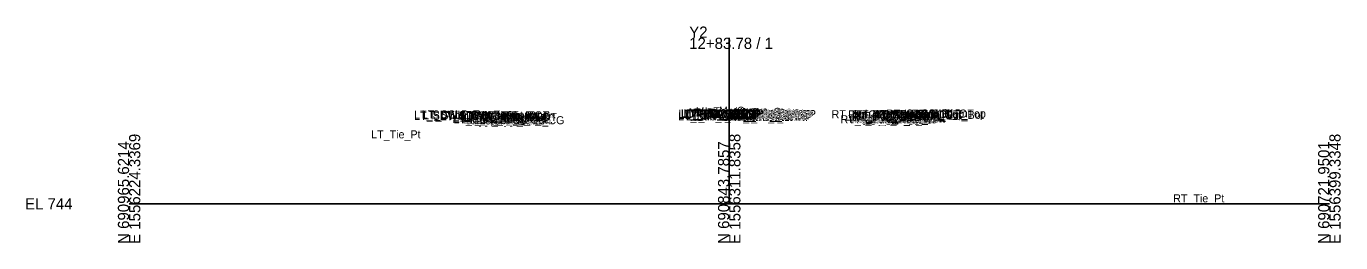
# Model space of a CAD drawing. Extents: x -26 to 4229, y -10 to 9523.
# Drawn here: x -25.7 to 302.8, y 2990.3 to 3044.3 of the extents above; entities that cross this region are included whole.
import ezdxf

# ---------------------------------------------------------------- set-up
doc = ezdxf.new("R2010")
doc.units = 0
doc.layers.add('Default', color=7, linetype='Continuous')
doc.layers.add('Exist Cross Section Cell', color=7, linetype='Continuous')

msp = doc.modelspace()

# ---------------------------------------------------------------- linework, layer by layer
at = {"layer": 'Exist Cross Section Cell'}
for p, q in [((150, 3000), (150, 3041.45)), ((0, 3000), (150, 3000)), ((150, 3000), (300, 3000))]:
    msp.add_line(p, q, dxfattribs=at)

# ---------------------------------------------------------------- texts
at = {"layer": 'Default'}
for s, height, p in [('LT_SDWK_Out_Top', 2, (71.24, 3021.29)), ('LT_SDWK_Out_Bot', 2, (71.27, 3020.96)), ('LT_CSLP_Pnt', 2, (73.17, 3021.32)), ('LT_Sub_Trench_Out_DLT', 2, (73.49, 3021.12)), ('LT_SDWK_In_Top', 2, (77.86, 3021.19)), ('LT_SDWK_In_Bot', 2, (77.89, 3020.86)), ('LT_CG_Top_Face', 2, (82.76, 3021.08)), ('LT_CG_Top_BOC', 2, (83.28, 3021.08)), ('LT_CG_Top_Gut', 2, (83.74, 3020.58)), ('LT_PV1_OEOT', 2, (88.24, 3020.7)), ('LT_Sub_OEEOP', 2, (137.22, 3020.83)), ('LT_PV2_OEEOP', 2, (137.32, 3021.46)), ('LT_PV3_OEEOP', 2, (137.32, 3021.21)), ('LT_PV1_OEEOP', 2, (137.88, 3021.58)), ('LT_PV2_IEEOP', 2, (137.96, 3021.46)), ('LT_PV1_IEEOP', 2, (138.53, 3021.58)), ('LT_PV2_PGL1', 2, (138.89, 3021.46)), ('LT_PV3_PGL1', 2, (138.89, 3021.21)), ('LT_PV2_PGL', 2, (139.22, 3021.46)), ('LT_PV4_PGL', 2, (139.22, 3020.83)), ('LT_PV1_PGL', 2, (139.79, 3021.71)), ('MI_Face In', 2, (139.91, 3021.87)), ('MI_Bot In', 2, (140.89, 3021.71)), ('MI_Top In', 2, (141.62, 3022.12)), ('MI_Crown', 2, (147.45, 3022.24)), ('RT_Sub_OEEOP', 2, (149.92, 3020.66)), ('RT_PV2_OEEOP', 2, (150.01, 3021.28)), ('RT_PV3_OEEOP', 2, (150.01, 3021.03)), ('RT_PV1_OEEOP', 2, (150.58, 3021.41)), ('RT_PV2_IEEOP', 2, (150.66, 3021.28)), ('MI_Face Out', 2, (151.01, 3021.7)), ('MI_Top Out', 2, (151.22, 3021.95)), ('RT_PV1_IEEOP', 2, (151.22, 3021.41)), ('RT_PV2_PGL1', 2, (151.58, 3021.28)), ('RT_PV3_PGL1', 2, (151.58, 3021.03)), ('RT_PV2_PGL', 2, (151.92, 3021.28)), ('RT_PV4_PGL', 2, (151.92, 3020.66)), ('MI_Bot Out', 2, (152.01, 3021.53)), ('RT_PV1_PGL', 2, (152.48, 3021.53)), ('RT_Sub_Trench_Out_DLT', 2, (175.59, 3021.36)), ('RT_CG_Top_Face', 2, (179.71, 3021.32)), ('RT_PV2_OEOT', 2, (180.63, 3020.69)), ('RT_CG_Top_Gut', 2, (180.69, 3020.82)), ('RT_PV1_OEOT', 2, (181.19, 3020.94)), ('RT_CG_Top_BOC', 2, (181.24, 3021.32)), ('RT_SDWK_In_Top', 2, (185.81, 3021.43)), ('RT_SDWK_In_Bot', 2, (185.84, 3021.1)), ('RT_SDWK_Out_Top', 2, (189.19, 3021.53)), ('RT_SDWK_Out_Bot', 2, (189.22, 3021.2)), ('RT_Shld_O', 2, (195.54, 3021.52)), ('CSLP_Pnt', 2, (197.87, 3021.56)), ('LT_CG1_Shelf_Out', 2, (81.05, 3020.05)), ('LT_CG_Bot_BOC', 2, (83.31, 3020.06)), ('LT_Sub_OEOP', 2, (84.36, 3019.8)), ('LT_Sub_OEOT_CG', 2, (84.87, 3019.86)), ('LT_CG_Bot_IE', 2, (87.41, 3020.11)), ('LT_Sub_OEOT', 2, (87.58, 3019.82)), ('LT_PV2_OEOT', 2, (87.67, 3020.45)), ('LT_PV3_OEOT', 2, (87.67, 3020.2)), ('RT_Sub_OEOT_CG', 2, (177.82, 3020.1)), ('RT_CG1_Shelf_Out', 2, (180, 3020.29)), ('RT_CG_Bot_IE', 2, (180.37, 3020.35)), ('RT_Sub_OEOT', 2, (180.53, 3020.06)), ('RT_PV3_OEOT', 2, (180.63, 3020.44)), ('RT_CG_Bot_BOC', 2, (181.27, 3020.3)), ('RT_Sub_OEOP', 2, (183.82, 3020.04)), ('LT_Tie_Pt', 2, (60.51, 3016.34)), ('-', 0.0001, (0, 3000)), ('-', 0.0001, (0, 3000)), ('-', 0.0001, (0, 3000)), ('-', 0.0001, (0, 3000)), ('-', 0.0001, (0, 3000)), ('-', 0.0001, (0, 3000)), ('-', 0.0001, (0, 3000)), ('-', 0.0001, (0, 3000)), ('-', 0.0001, (0, 3000)), ('RT_Tie_Pt', 2, (260.97, 3000.37))]:
    msp.add_text(s, height=height, dxfattribs=at).set_placement(p)
at = {"layer": 'Exist Cross Section Cell'}
for s, p in [('Y2', (140, 3041.45)), ('12+83.78 / 1', (140, 3038.65)), ('EL 744', (-26, 2998.6))]:
    msp.add_text(s, height=2.8, dxfattribs=at).set_placement(p)
for s, p in [('E 1556224.3369', (2.8, 2990)), ('E 1556311.8358', (152.8, 2990)), ('E 1556399.3348', (302.8, 2990)), ('N 690965.6214', (0, 2990)), ('N 690843.7857', (150, 2990)), ('N 690721.9501', (300, 2990))]:
    msp.add_text(s, height=2.8, rotation=90, dxfattribs=at).set_placement(p)

doc.saveas('drawing.dxf')
